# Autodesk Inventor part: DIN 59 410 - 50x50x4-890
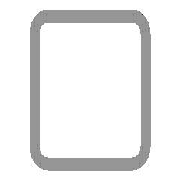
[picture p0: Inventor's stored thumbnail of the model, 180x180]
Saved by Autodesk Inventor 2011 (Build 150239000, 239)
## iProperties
Created: 2010-02
Part Number: DIN 59 410 - 50x50x4-890
Material: Steel, A36
Description: Hot formed square steel tubes
Document SubType Name: Modellieren
Standard: DIN
Designer: PC
Standards Organization: DIN
Language: en-US
Size Designation: 50x50x4
Categories: <MemberInstance><Categories><Category DisplayName="Structural Shapes" InternalName="089c4875-fa83-4c05-b084-43b9cc11f5ed" Mnemonic="GRDR"><CategoryParameter Dis
Stock Number: 50x50x4
Density: 7.85 g/cm^3
Author: PC
IsCustomPart: 1
G_L: 890.000 mm
G_W: 50.000 mm
G_H: 50.000 mm
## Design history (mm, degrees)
node "Start plane"
node "End plane"
sketch "Sketch"
  geometry: L1 (-17, 25)-(17, 25); L2 (25, 17)-(25, -17); L3 (17, -25)-(-17, -25); L4 (-25, -17)-(-25, 17); L5 (-37.32, 0)-(37.32, 0) reference; L6 (0, -37.32)-(0, 37.32) reference; L7 (-17, 21)-(17, 21); L8 (21, 17)-(21, -17); L9 (17, -21)-(-17, -21); L10 (-21, -17)-(-21, 17); A1 r 8 centre (-17, 17) between (-17, 25) and (-25, 17); A2 r 8 centre (17, 17) between (25, 17) and (17, 25); A3 r 8 centre (17, -17) between (17, -25) and (25, -17); A4 r 8 centre (-17, -17) between (-25, -17) and (-17, -25); A5 r 4 centre (-17, 17) between (-17, 21) and (-21, 17); A6 r 4 centre (17, 17) between (21, 17) and (17, 21); A7 r 4 centre (17, -17) between (17, -21) and (21, -17); A8 r 4 centre (-17, -17) between (-21, -17) and (-17, -21); 3 further points
  constraints: 16 end point, 16 point on circle, 8 centre point, 8 tangent, 6 point on line, 4 parallel, 3 equal radius, 3 perpendicular, 1 horizontal, 7 other
  dimensions: "b" = 50 distance of point (-25, 25) point (25, 25); "msp_r" = 8 radius of A1 (= 2 x ParT); "d8" = 25 distance between parallel lines of L4 L6 (= d9); "d9" = 25 distance between parallel lines of L3 L5 (= 0.5 x b); "d10" = 4 distance between parallel lines of L3 L9 (= ParT)
extrude "Body" new body sketch "Sketch" taper "d4" = 0 deg; stored distance "NLG" = 10
node "Driven Length"
  sketch "Sketch2"
    geometry: L1 (0, 0)-(10, 0) reference
    constraints: 2 end point, 1 horizontal
  workplane "Work Plane3"
  sketch "Sketch3"
    geometry: L1 (-2, 0)-(12, 0) reference; L2 (-2, 890)-(12, 890) reference
    dimensions: "d14" = 890 distance between parallel lines of L1 L2 (derived)
body "Solid1"
other parameters: "ParT" = 4, "G_OFFSET_START" = 0 [user parameter; used in 1 equation term], "G_OFFSET_END" = 0 [user parameter; used in 1 equation term], "d11" = 0 (computed from G_OFFSET_START), "G_L" = 890 (= d14) [user parameter], "d13" = 90 deg
